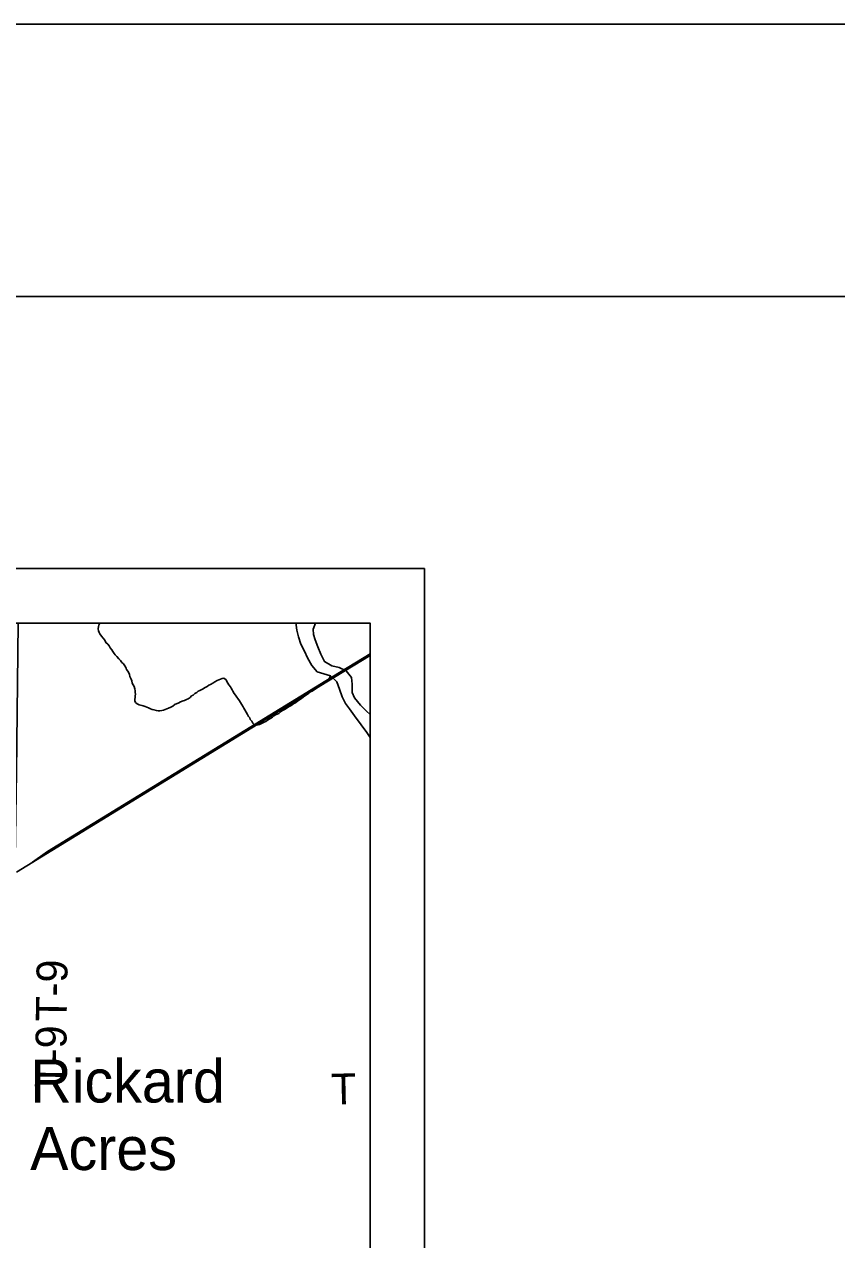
# Model space of a CAD drawing. Extents: x 0 to 34, y 0 to 22.
# Drawn here: x 8.264 to 9.758, y 19.765 to 21.998 of the extents above; entities that cross this region are included whole.
import ezdxf

# ---------------------------------------------------------------- set-up
doc = ezdxf.new("R2010")
doc.units = 0
for name, color, linetype in [('GM_X_Corporation', 7, 'Continuous'), ('GM_X_Major_River', 7, 'Continuous'), ('GM_X_Minor_River', 7, 'Continuous'), ('GM_X_Rail_Line', 7, 'Continuous'), ('GM_X_Township_Road_Text', 7, 'Continuous'), ('GM_X_Unincorporated_Text', 7, 'Continuous'), ('SH_Border', 7, 'Continuous'), ('SH_Cut_Line', 7, 'Continuous'), ('SH_Data', 7, 'Continuous')]:
    doc.layers.add(name, color=color, linetype=linetype)

msp = doc.modelspace()

# ---------------------------------------------------------------- linework, layer by layer
at = {"layer": 'GM_X_Corporation'}
msp.add_lwpolyline([(8.9, 19.3874), (8.9, 20.898), (8.2532, 20.898), (8.2498, 20.6242), (8.2459, 20.3463), (8.2437, 20.1914), (8.2424, 20.1172), (8.2412, 20.0451), (8.2346, 19.7113)], dxfattribs=at)
at = {"layer": 'GM_X_Major_River'}
for points in [[(8.7639, 20.898), (8.7639, 20.8945), (8.7656, 20.8849), (8.7683, 20.8727), (8.7729, 20.8596), (8.7794, 20.8466), (8.7847, 20.8339), (8.7927, 20.8204), (8.803, 20.8083), (8.8151, 20.8046), (8.8271, 20.8013), (8.839, 20.7903), (8.8439, 20.7765), (8.8489, 20.7623), (8.8546, 20.7504), (8.8619, 20.7407), (8.8711, 20.7276), (8.8836, 20.7113), (8.8938, 20.6973), (8.9, 20.6881)], [(8.9, 20.7303), (8.8937, 20.7365), (8.8826, 20.7474), (8.8712, 20.761), (8.8669, 20.7706), (8.8669, 20.7858), (8.8657, 20.798), (8.8562, 20.8104), (8.8431, 20.8164), (8.8295, 20.8194), (8.8164, 20.8274), (8.8096, 20.8409), (8.8042, 20.8543), (8.7989, 20.8673), (8.7961, 20.8773), (8.7952, 20.8868), (8.7995, 20.898)]]:
    msp.add_lwpolyline(points, dxfattribs=at)
at = {"layer": 'GM_X_Minor_River'}
for points in [[(8.403, 20.898), (8.403, 20.8979), (8.4014, 20.8942), (8.4006, 20.8915), (8.4001, 20.8873), (8.4008, 20.8839), (8.4019, 20.8808), (8.4033, 20.8782), (8.4063, 20.8743), (8.4096, 20.8704), (8.4122, 20.8665), (8.4144, 20.8623), (8.4177, 20.8592), (8.4203, 20.8565), (8.4225, 20.8523), (8.4255, 20.8488), (8.4269, 20.8461), (8.4295, 20.8422), (8.4317, 20.8395), (8.4347, 20.8368), (8.438, 20.8325), (8.441, 20.829), (8.4436, 20.8259), (8.4465, 20.8232), (8.4491, 20.8193), (8.4517, 20.8155), (8.4524, 20.8128), (8.4546, 20.8097), (8.4564, 20.8066), (8.4575, 20.8036), (8.4582, 20.8001), (8.4596, 20.7974), (8.4607, 20.7948), (8.4622, 20.7917), (8.4628, 20.7879), (8.4647, 20.7848), (8.4661, 20.7813), (8.4679, 20.7771), (8.4682, 20.7737), (8.4685, 20.7706), (8.4688, 20.7676), (8.4684, 20.7642), (8.468, 20.7615), (8.4675, 20.7581), (8.4678, 20.755), (8.4689, 20.7524), (8.4719, 20.75), (8.4756, 20.748), (8.4805, 20.7468), (8.4832, 20.746), (8.4866, 20.7447), (8.4899, 20.7435), (8.4929, 20.7423), (8.4963, 20.7407), (8.4993, 20.7395), (8.5027, 20.7387), (8.5073, 20.7374), (8.5107, 20.737)], [(8.5107, 20.737), (8.5133, 20.7369), (8.5171, 20.7372), (8.5202, 20.7383), (8.5236, 20.739), (8.5267, 20.7404), (8.5294, 20.7419), (8.5339, 20.7437), (8.5374, 20.7455), (8.5416, 20.7489), (8.5443, 20.75), (8.5482, 20.7518), (8.5516, 20.7536), (8.5562, 20.7554), (8.5589, 20.7561), (8.5627, 20.7579), (8.5654, 20.759), (8.5696, 20.7616), (8.5719, 20.7646), (8.5746, 20.7657), (8.5781, 20.7686), (8.5816, 20.7708), (8.5843, 20.7727), (8.5869, 20.7741), (8.5896, 20.7756), (8.5931, 20.777), (8.5958, 20.7789), (8.6004, 20.7814), (8.6035, 20.784), (8.6069, 20.7855), (8.6111, 20.7877), (8.6146, 20.7899), (8.6192, 20.7928), (8.6223, 20.7939), (8.6249, 20.795), (8.628, 20.7964), (8.6314, 20.7967), (8.6352, 20.7936), (8.637, 20.7905), (8.6388, 20.7878), (8.6406, 20.7844), (8.6432, 20.7809), (8.6447, 20.7782), (8.6465, 20.7755), (8.648, 20.7728), (8.6505, 20.7686), (8.6528, 20.7655), (8.6553, 20.762), (8.6572, 20.7593), (8.6597, 20.7554), (8.6619, 20.7523), (8.6638, 20.7489), (8.6667, 20.7443), (8.6682, 20.7416), (8.6696, 20.7385), (8.6722, 20.7342), (8.6744, 20.7304), (8.6766, 20.7265), (8.6788, 20.7238), (8.6799, 20.7208), (8.6824, 20.7177), (8.6846, 20.7142), (8.6872, 20.7119), (8.6906, 20.7114), (8.6941, 20.7113), (8.6967, 20.712), (8.6994, 20.7131), (8.7029, 20.7146), (8.7055, 20.716), (8.7082, 20.7175), (8.7113, 20.7197), (8.7144, 20.7215), (8.7175, 20.7234), (8.7205, 20.7252), (8.7232, 20.7274), (8.7259, 20.7293), (8.729, 20.7307), (8.7321, 20.7322), (8.7355, 20.7348), (8.739, 20.7374), (8.7425, 20.7392), (8.7459, 20.7414), (8.7501, 20.744), (8.7536, 20.7458), (8.7567, 20.748), (8.7598, 20.7502), (8.7628, 20.7517), (8.7671, 20.755), (8.7702, 20.7572), (8.7744, 20.7602), (8.7771, 20.762), (8.7802, 20.7642), (8.7829, 20.7661), (8.7875, 20.7694), (8.7902, 20.7716), (8.7933, 20.7731), (8.7963, 20.7749), (8.799, 20.7764), (8.8029, 20.7793), (8.8056, 20.7816), (8.8083, 20.7834)], [(8.8083, 20.7834), (8.811, 20.7856), (8.8152, 20.7882), (8.8179, 20.7897), (8.8214, 20.793), (8.8248, 20.7956), (8.8271, 20.8013)]]:
    msp.add_lwpolyline(points, dxfattribs=at)
at = {"layer": 'GM_X_Rail_Line'}
for points in [[(8.2498, 20.4407), (8.8203, 20.7899), (8.9, 20.8387)], [(8.2796, 20.4589), (8.3069, 20.4785), (8.819, 20.792), (8.9, 20.8416)]]:
    msp.add_lwpolyline(points, dxfattribs=at)
at = {"layer": 'SH_Border'}
msp.add_lwpolyline([(1.5, 21.498), (33.5, 21.498), (33.5, 0.498), (1.5, 0.498)], close=True, dxfattribs=at)
at = {"layer": 'SH_Cut_Line'}
msp.add_lwpolyline([(0, -0.002), (34, -0.002), (34, 21.998), (0, 21.998)], close=True, dxfattribs=at)
at = {"layer": 'SH_Data'}
for p, q in [((2, 20.998), (9, 20.998)), ((9, 20.998), (9, 13.998)), ((2.1, 20.898), (8.9, 20.898)), ((8.9, 20.898), (8.9, 14.098))]:
    msp.add_line(p, q, dxfattribs=at)

# ---------------------------------------------------------------- texts
at = {"layer": 'GM_X_Township_Road_Text'}
for s, height, rotation, p in [('T-9', 0.05682, 89.0397, (8.3422, 20.1655)), ('T-9', 0.05682, 89.0447, (8.3405, 20.0445)), ('T', 0.0568, 1.2687, (8.8289, 20.0133))]:
    msp.add_text(s, height=height, rotation=rotation, dxfattribs=at).set_placement(p)
at = {"layer": 'GM_X_Unincorporated_Text'}
for s, p in [('Rickard', (8.2752, 20.0173)), ('Acres', (8.2752, 19.8932))]:
    msp.add_text(s, height=0.07898, rotation=0, dxfattribs=at).set_placement(p)

doc.saveas('drawing.dxf')
